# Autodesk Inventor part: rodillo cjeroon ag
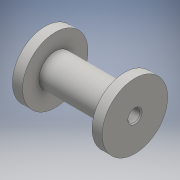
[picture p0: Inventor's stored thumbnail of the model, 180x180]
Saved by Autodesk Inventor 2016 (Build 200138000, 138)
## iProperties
Created: 2016-06
Part Number: rodillo cjeroon ag
Material: Genérico
Document SubType Name: Modeling
Designer: adm
Density: 1 g/cm^3
Appearance: Valor por defecto
Author: adm
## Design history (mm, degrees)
sketch "Boceto1"
  geometry: L1 (0, 0)-(0, 16); L2 (0, 16)-(5, 16); L3 (5, 16)-(5, 8); L4 (5, 8)-(39, 8); L5 (39, 8)-(39, 16); L6 (39, 16)-(44, 16); L7 (0, 0)-(44, 0); L8 (44, 0)-(44, 16)
  constraints: 16 end point, 5 perpendicular, 2 vertical, 1 horizontal, 1 horizontal alignment
  dimensions: "d0" = 44 distance of L1.start L7.end; "d1" = 5 distance of L1.end L2.end; "d2" = 5 distance of L5.end L6.end; "d3" = 16 distance between parallel lines of L7 L2; "d4" = 8 distance between parallel lines of L7 L4
revolve "Revolución1" sketch "Boceto1" stored, may be unused: angle "d5" = 90 deg
sketch "Boceto2"
  geometry: C1 r 3 at (0, 0); 1 further point
  constraints: 1 centre point, 1 coincident
  dimensions: "d6" = 6 diameter of C1
extrude "Extrusión1" cut sketch "Boceto2" stored distance "d7" = 10; taper "d8" = 0 deg
node "Plano de trabajo1"
sketch "Boceto3"
  geometry: L1 (0, 16)-(0, -16) reference; L2 (-44, 16)-(-44, -16) reference; C1 r 1 at (-34, 0); C2 r 1 at (-10, 0); 2 further points
  constraints: 2 centre point
  dimensions: "d10" = 2 diameter of C1; "d11" = 2 diameter of C2; "d12" = 10 distance from line of C2.centre L1
extrude "Extrusión2" cut sketch "Boceto3" distance "d14" = 10; taper "d15" = 0 deg
chamfer "Chaflán1" distance "d16" = 0.5; stored, may be unused: second distance "d17" = 2, angle "d18" = 45 deg
node "Sólido1"
other parameters: "d9" = 9
